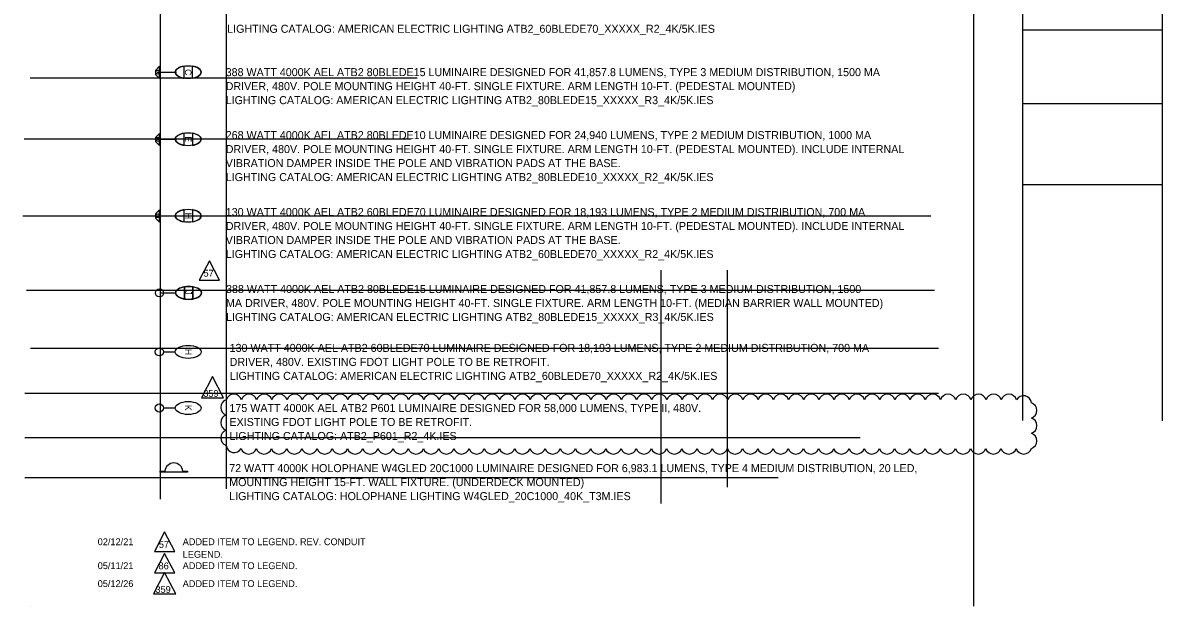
# Model space of a CAD drawing. Extents: x -0.7 to 15.2, y -0.9 to 9.6.
# Drawn here: x -0.62 to 9.35, y -0.9 to 4.21 of the extents above; entities that cross this region are included whole.
import ezdxf

# ---------------------------------------------------------------- set-up
doc = ezdxf.new("R2010")
doc.units = 0
for name, color, linetype in [('ActivePointCell_dp', 7, 'Continuous'), ('AdhocPoint_dp', 7, 'Continuous'), ('Cloud_dp', 7, 'Continuous'), ('LightingMisc', 7, 'Continuous'), ('Miscellaneous2', 7, 'Continuous'), ('Miscellaneous3', 7, 'Continuous'), ('Miscellaneous8', 7, 'Continuous'), ('Miscellaneous9', 7, 'Continuous'), ('ScratchEle_dp', 7, 'Continuous'), ('TextMisc', 7, 'Continuous'), ('TextShtNo', 7, 'Continuous')]:
    doc.layers.add(name, color=color, linetype=linetype)

msp = doc.modelspace()

# ---------------------------------------------------------------- linework, layer by layer
at = {"layer": 'ActivePointCell_dp'}
for p, q in [((7.7, -0.9), (7.7, 9.6)), ((8.1255, 9.4869), (8.1255, 0.7251)), ((9.3472, 9.4838), (9.3472, 0.7219)), ((0.5844, 9.2534), (0.5844, 0.0367)), ((1.1641, 0.1282), (1.1641, 9.1337)), ((2.8316, 3.722), (-0.5519, 3.722)), ((2.7789, 3.1858), (-0.6046, 3.1858)), ((7.3238, 2.5135), (-0.6178, 2.5135)), ((4.9633, 2.0414), (4.9633, 0)), ((5.5423, 2.0414), (5.5423, 0.1403)), ((7.3568, 1.862), (-0.5847, 1.862)), ((7.39, 1.3545), (-0.5516, 1.3545)), ((7.39, 0.9614), (-0.599, 0.9614)), ((6.7052, 0.5747), (-0.599, 0.5747)), ((5.9878, 0.2247), (-0.599, 0.2247))]:
    msp.add_line(p, q, dxfattribs=at)
at = {"layer": 'Cloud_dp'}
for points in [[(1.0137, 2.1234), (0.9257, 1.9538), (1.1017, 1.9538)], [(1.0412, 1.1101), (0.9444, 0.9236), (1.138, 0.9236)], [(0.6228, -0.2504), (0.5348, -0.42), (0.7109, -0.42)], [(0.6228, -0.4378), (0.5348, -0.6074), (0.7109, -0.6074)], [(0.6228, -0.6056), (0.526, -0.7921), (0.7197, -0.7921)]]:
    msp.add_lwpolyline(points, close=True, dxfattribs=at)
for centre, radius, start, end in [((1.1825, 0.8395), 0.0697, 107.5, 252.5), ((1.228, 0.885), 0.0697, 17.5, 162.5), ((1.3609, 0.885), 0.0697, 17.5, 162.5), ((1.4939, 0.885), 0.0697, 17.5, 162.5), ((1.6268, 0.885), 0.0697, 17.5, 162.5), ((1.7597, 0.885), 0.0697, 17.5, 162.5), ((1.8926, 0.885), 0.0697, 17.5, 162.5), ((2.0255, 0.885), 0.0697, 17.5, 162.5), ((2.1584, 0.885), 0.0697, 17.5, 162.5), ((2.2913, 0.885), 0.0697, 17.5, 162.5), ((2.4242, 0.885), 0.0697, 17.5, 162.5), ((2.5571, 0.885), 0.0697, 17.5, 162.5), ((2.69, 0.885), 0.0697, 17.5, 162.5), ((2.8229, 0.885), 0.0697, 17.5, 162.5), ((2.9559, 0.885), 0.0697, 17.5, 162.5), ((3.0888, 0.885), 0.0697, 17.5, 162.5), ((3.2217, 0.885), 0.0697, 17.5, 162.5), ((3.3546, 0.885), 0.0697, 17.5, 162.5), ((3.4875, 0.885), 0.0697, 17.5, 162.5), ((3.6204, 0.885), 0.0697, 17.5, 162.5), ((3.7533, 0.885), 0.0697, 17.5, 162.5), ((3.8862, 0.885), 0.0697, 17.5, 162.5), ((4.0191, 0.885), 0.0697, 17.5, 162.5), ((4.152, 0.885), 0.0697, 17.5, 162.5), ((4.2849, 0.885), 0.0697, 17.5, 162.5), ((4.4178, 0.885), 0.0697, 17.5, 162.5), ((4.5508, 0.885), 0.0697, 17.5, 162.5), ((4.6837, 0.885), 0.0697, 17.5, 162.5), ((4.8166, 0.885), 0.0697, 17.5, 162.5), ((4.9495, 0.885), 0.0697, 17.5, 162.5), ((5.0824, 0.885), 0.0697, 17.5, 162.5), ((5.2153, 0.885), 0.0697, 17.5, 162.5), ((5.3482, 0.885), 0.0697, 17.5, 162.5), ((5.4811, 0.885), 0.0697, 17.5, 162.5), ((5.614, 0.885), 0.0697, 17.5, 162.5), ((5.7469, 0.885), 0.0697, 17.5, 162.5), ((5.8798, 0.885), 0.0697, 17.5, 162.5), ((6.0128, 0.885), 0.0697, 17.5, 162.5), ((6.1457, 0.885), 0.0697, 17.5, 162.5), ((6.2786, 0.885), 0.0697, 17.5, 162.5), ((6.4115, 0.885), 0.0697, 17.5, 162.5), ((6.5444, 0.885), 0.0697, 17.5, 162.5), ((6.6773, 0.885), 0.0697, 17.5, 162.5), ((6.8102, 0.885), 0.0697, 17.5, 162.5), ((6.9431, 0.885), 0.0697, 17.5, 162.5), ((7.076, 0.885), 0.0697, 17.5, 162.5), ((7.2089, 0.885), 0.0697, 17.5, 162.5), ((7.3418, 0.885), 0.0697, 17.5, 162.5), ((7.4748, 0.885), 0.0697, 17.5, 162.5), ((7.6077, 0.885), 0.0697, 17.5, 162.5), ((7.7406, 0.885), 0.0697, 17.5, 162.5), ((7.8735, 0.885), 0.0697, 17.5, 162.5), ((8.0064, 0.885), 0.0697, 17.5, 162.5), ((8.1337, 0.8722), 0.0696, 5.94047, 150.94047), ((8.182, 0.8129), 0.0697, 287.5, 72.5), ((1.1825, 0.7066), 0.0697, 107.5, 252.5), ((8.182, 0.68), 0.0697, 287.5, 72.5), ((1.1825, 0.5737), 0.0697, 107.5, 252.5), ((8.182, 0.5471), 0.0697, 287.5, 72.5), ((1.2308, 0.5145), 0.0696, 185.94047, 330.94047), ((1.3582, 0.5016), 0.0697, 197.5, 342.5), ((1.4911, 0.5016), 0.0697, 197.5, 342.5), ((1.624, 0.5016), 0.0697, 197.5, 342.5), ((1.7569, 0.5016), 0.0697, 197.5, 342.5), ((1.8898, 0.5016), 0.0697, 197.5, 342.5), ((2.0227, 0.5016), 0.0697, 197.5, 342.5), ((2.1556, 0.5016), 0.0697, 197.5, 342.5), ((2.2885, 0.5016), 0.0697, 197.5, 342.5), ((2.4214, 0.5016), 0.0697, 197.5, 342.5), ((2.5543, 0.5016), 0.0697, 197.5, 342.5), ((2.6873, 0.5016), 0.0697, 197.5, 342.5), ((2.8202, 0.5016), 0.0697, 197.5, 342.5), ((2.9531, 0.5016), 0.0697, 197.5, 342.5), ((3.086, 0.5016), 0.0697, 197.5, 342.5), ((3.2189, 0.5016), 0.0697, 197.5, 342.5), ((3.3518, 0.5016), 0.0697, 197.5, 342.5), ((3.4847, 0.5016), 0.0697, 197.5, 342.5), ((3.6176, 0.5016), 0.0697, 197.5, 342.5), ((3.7505, 0.5016), 0.0697, 197.5, 342.5), ((3.8834, 0.5016), 0.0697, 197.5, 342.5), ((4.0163, 0.5016), 0.0697, 197.5, 342.5), ((4.1493, 0.5016), 0.0697, 197.5, 342.5), ((4.2822, 0.5016), 0.0697, 197.5, 342.5), ((4.4151, 0.5016), 0.0697, 197.5, 342.5), ((4.548, 0.5016), 0.0697, 197.5, 342.5), ((4.6809, 0.5016), 0.0697, 197.5, 342.5), ((4.8138, 0.5016), 0.0697, 197.5, 342.5), ((4.9467, 0.5016), 0.0697, 197.5, 342.5), ((5.0796, 0.5016), 0.0697, 197.5, 342.5), ((5.2125, 0.5016), 0.0697, 197.5, 342.5), ((5.3454, 0.5016), 0.0697, 197.5, 342.5), ((5.4783, 0.5016), 0.0697, 197.5, 342.5), ((5.6112, 0.5016), 0.0697, 197.5, 342.5), ((5.7442, 0.5016), 0.0697, 197.5, 342.5), ((5.8771, 0.5016), 0.0697, 197.5, 342.5), ((6.01, 0.5016), 0.0697, 197.5, 342.5), ((6.1429, 0.5016), 0.0697, 197.5, 342.5), ((6.2758, 0.5016), 0.0697, 197.5, 342.5), ((6.4087, 0.5016), 0.0697, 197.5, 342.5), ((6.5416, 0.5016), 0.0697, 197.5, 342.5), ((6.6745, 0.5016), 0.0697, 197.5, 342.5), ((6.8074, 0.5016), 0.0697, 197.5, 342.5), ((6.9403, 0.5016), 0.0697, 197.5, 342.5), ((7.0732, 0.5016), 0.0697, 197.5, 342.5), ((7.2062, 0.5016), 0.0697, 197.5, 342.5), ((7.3391, 0.5016), 0.0697, 197.5, 342.5), ((7.472, 0.5016), 0.0697, 197.5, 342.5), ((7.6049, 0.5016), 0.0697, 197.5, 342.5), ((7.7378, 0.5016), 0.0697, 197.5, 342.5), ((7.8707, 0.5016), 0.0697, 197.5, 342.5), ((8.0036, 0.5016), 0.0697, 197.5, 342.5), ((8.1365, 0.5016), 0.0697, 197.5, 342.5)]:
    msp.add_arc(centre, radius, start, end, dxfattribs=at)
at = {"layer": 'LightingMisc'}
for p, q in [((0.584, 0.2734), (0.5839, 0.2814)), ((0.5839, 0.2814), (0.6241, 0.2814)), ((0.8228, 0.2739), (0.584, 0.2734)), ((0.7826, 0.2818), (0.8228, 0.2819)), ((0.8228, 0.2819), (0.8228, 0.2739))]:
    msp.add_line(p, q, dxfattribs=at)
msp.add_arc((0.7034, 0.2737), 0.0796, 5.86956, 174.39115, dxfattribs=at)
at = {"layer": 'Miscellaneous2'}
msp.add_ellipse((0.8323, 1.8418), major_axis=(-0.1133, 0), ratio=0.5, start_param=4.391241, end_param=4.391271, dxfattribs=at)
at = {"layer": 'Miscellaneous3'}
msp.add_line((8.1215, 4.1449), (9.3431, 4.1449), dxfattribs=at)
at = {"layer": 'Miscellaneous8'}
msp.add_line((8.1215, 3.4986), (9.342, 3.4986), dxfattribs=at)
at = {"layer": 'Miscellaneous9'}
msp.add_line((8.122, 2.7896), (9.3437, 2.7896), dxfattribs=at)
at = {"layer": 'ScratchEle_dp'}
for p, q in [((0.7932, 3.7193), (0.7932, 3.8268)), ((0.8647, 3.8268), (0.8647, 3.7193)), ((0.5583, 3.7731), (0.7274, 3.7731)), ((0.7936, 3.132), (0.7936, 3.2395)), ((0.8651, 3.2395), (0.8651, 3.132)), ((0.5587, 3.1858), (0.7277, 3.1858)), ((0.5587, 2.5167), (0.7277, 2.5167)), ((0.7936, 2.463), (0.7936, 2.5705)), ((0.8651, 2.5705), (0.8651, 2.463)), ((0.7965, 1.7881), (0.7965, 1.8956)), ((0.7965, 1.8944), (0.7965, 1.7881)), ((0.868, 1.8956), (0.868, 1.7881)), ((0.868, 1.7881), (0.868, 1.8956)), ((0.5929, 1.8415), (0.7238, 1.8415)), ((0.6113, 1.3255), (0.7161, 1.3255)), ((0.6113, 0.8345), (0.7161, 0.8345))]:
    msp.add_line(p, q, dxfattribs=at)
for points in [[(0.5425, 3.789), (0.5426, 3.7532), (0.5783, 3.7175), (0.5782, 3.8248)], [(0.5429, 3.2017), (0.543, 3.1659), (0.5786, 3.1302), (0.5786, 3.2374)], [(0.5429, 2.5327), (0.543, 2.4969), (0.5786, 2.4612), (0.5786, 2.5684)]]:
    msp.add_lwpolyline(points, close=True, dxfattribs=at)
for centre, radius in [((0.5617, 3.7728), 0.0163), ((0.562, 3.1855), 0.0163), ((0.562, 2.5165), 0.0163), ((0.5779, 1.8415), 0.0354), ((0.5779, 1.8415), 0.0354), ((0.576, 1.3255), 0.0354), ((0.576, 0.8345), 0.0354)]:
    msp.add_circle(centre, radius, dxfattribs=at)
for centre in [(0.8289, 3.7731), (0.8293, 3.1858), (0.8293, 2.5167), (0.8323, 1.8418), (0.8293, 1.3255), (0.8293, 0.8345)]:
    msp.add_ellipse(centre, major_axis=(-0.1133, 0), ratio=0.5, dxfattribs=at)
for centre, start_param, end_param in [((0.8289, 3.7731), 5.033538, 6.283185), ((0.8289, 3.7731), 1.891945, 4.391241), ((0.8289, 3.7731), 0, 0.847605), ((0.8289, 3.7731), 0.847605, 1.249648), ((0.8293, 3.1858), 5.033538, 6.283185), ((0.8293, 3.1858), 1.891945, 4.391241), ((0.8293, 3.1858), 0, 0.847605), ((0.8293, 3.1858), 0.847605, 1.249648), ((0.8293, 2.5167), 5.033538, 6.283185), ((0.8293, 2.5167), 0, 0.847605), ((0.8293, 2.5167), 1.891945, 4.391241), ((0.8293, 2.5167), 0.847605, 1.249648), ((0.8323, 1.8418), 5.033538, 6.283185), ((0.8323, 1.8418), 4.391271, 5.033538), ((0.8323, 1.8418), 1.891945, 4.391241), ((0.8323, 1.8418), 0, 0.847605), ((0.8323, 1.8418), 0.847605, 1.249648), ((0.8323, 1.8418), 1.249648, 1.891946)]:
    msp.add_ellipse(centre, major_axis=(-0.1133, 0), ratio=0.5, start_param=start_param, end_param=end_param, dxfattribs=at)
at = {"layer": 'TextMisc'}
msp.add_line((-0.55, -0.9), (-0.55, -0.9), dxfattribs=at)

# ---------------------------------------------------------------- texts
at = {"layer": 'AdhocPoint_dp'}
for s, p in [('LIGHTING CATALOG: AMERICAN ELECTRIC LIGHTING ATB2_60BLEDE70_XXXXX_R2_4K/5K.IES', (1.1699, 4.1176)), ('388 WATT 4000K AEL ATB2 80BLEDE15 LUMINAIRE DESIGNED FOR 41,857.8 LUMENS, TYPE 3 MEDIUM DISTRIBUTION, 1500 MA ', (1.1566, 3.7381)), ('DRIVER, 480V. POLE MOUNTING HEIGHT 40-FT. SINGLE FIXTURE. ARM LENGTH 10-FT. (PEDESTAL MOUNTED)', (1.1566, 3.6156)), ('LIGHTING CATALOG: AMERICAN ELECTRIC LIGHTING ATB2_80BLEDE15_XXXXX_R3_4K/5K.IES', (1.1566, 3.4931)), ('268 WATT 4000K AEL ATB2 80BLEDE10 LUMINAIRE DESIGNED FOR 24,940 LUMENS, TYPE 2 MEDIUM DISTRIBUTION, 1000 MA ', (1.157, 3.1875)), ('DRIVER, 480V. POLE MOUNTING HEIGHT 40-FT. SINGLE FIXTURE. ARM LENGTH 10-FT. (PEDESTAL MOUNTED). INCLUDE INTERNAL ', (1.157, 3.065)), ('VIBRATION DAMPER INSIDE THE POLE AND VIBRATION PADS AT THE BASE.', (1.157, 2.9425)), ('LIGHTING CATALOG: AMERICAN ELECTRIC LIGHTING ATB2_80BLEDE10_XXXXX_R2_4K/5K.IES', (1.157, 2.82)), ('130 WATT 4000K AEL ATB2 60BLEDE70 LUMINAIRE DESIGNED FOR 18,193 LUMENS, TYPE 2 MEDIUM DISTRIBUTION, 700 MA ', (1.1574, 2.5143)), ('DRIVER, 480V. POLE MOUNTING HEIGHT 40-FT. SINGLE FIXTURE. ARM LENGTH 10-FT. (PEDESTAL MOUNTED). INCLUDE INTERNAL ', (1.1574, 2.3918)), ('VIBRATION DAMPER INSIDE THE POLE AND VIBRATION PADS AT THE BASE.', (1.1574, 2.2693)), ('LIGHTING CATALOG: AMERICAN ELECTRIC LIGHTING ATB2_60BLEDE70_XXXXX_R2_4K/5K.IES', (1.1574, 2.1468)), ('388 WATT 4000K AEL ATB2 80BLEDE15 LUMINAIRE DESIGNED FOR 41,857.8 LUMENS, TYPE 3 MEDIUM DISTRIBUTION, 1500 ', (1.1594, 1.8408)), ('MA DRIVER, 480V. POLE MOUNTING HEIGHT 40-FT. SINGLE FIXTURE. ARM LENGTH 10-FT. (MEDIAN BARRIER WALL MOUNTED)', (1.1594, 1.7183)), ('LIGHTING CATALOG: AMERICAN ELECTRIC LIGHTING ATB2_80BLEDE15_XXXXX_R3_4K/5K.IES', (1.1594, 1.5958)), ('130 WATT 4000K AEL ATB2 60BLEDE70 LUMINAIRE DESIGNED FOR 18,193 LUMENS, TYPE 2 MEDIUM DISTRIBUTION, 700 MA ', (1.1912, 1.3255)), ('DRIVER, 480V. EXISTING FDOT LIGHT POLE TO BE RETROFIT.', (1.1912, 1.203)), ('LIGHTING CATALOG: AMERICAN ELECTRIC LIGHTING ATB2_60BLEDE70_XXXXX_R2_4K/5K.IES', (1.1912, 1.0805)), ('175 WATT 4000K AEL ATB2 P601 LUMINAIRE DESIGNED FOR 58,000 LUMENS, TYPE II, 480V.', (1.1895, 0.7995)), ('EXISTING FDOT LIGHT POLE TO BE RETROFIT.', (1.1895, 0.677)), ('LIGHTING CATALOG: ATB2_P601_R2_4K.IES', (1.1895, 0.5545)), ('72 WATT 4000K HOLOPHANE W4GLED 20C1000 LUMINAIRE DESIGNED FOR 6,983.1 LUMENS, TYPE 4 MEDIUM DISTRIBUTION, 20 LED, ', (1.1877, 0.2734)), ('MOUNTING HEIGHT 15-FT. WALL FIXTURE. (UNDERDECK MOUNTED)', (1.1877, 0.1509)), ('LIGHTING CATALOG: HOLOPHANE LIGHTING W4GLED_20C1000_40K_T3M.IES', (1.1877, 0.0284))]:
    msp.add_text(s, height=0.07, dxfattribs=at).set_placement(p)
at = {"layer": 'Cloud_dp'}
for s, p in [('57', (0.963, 1.984)), ('359', (0.9607, 0.9323)), ('02/12/21', (0.0373, -0.3659)), ('57', (0.5721, -0.3898)), ('ADDED ITEM TO LEGEND. REV. CONDUIT ', (0.7806, -0.3659)), ('LEGEND.', (0.7806, -0.4759)), ('05/11/21', (0.0373, -0.5754)), ('86', (0.5695, -0.5772)), ('ADDED ITEM TO LEGEND.', (0.7806, -0.5754)), ('05/12/26', (0.0373, -0.7324)), ('ADDED ITEM TO LEGEND.', (0.7806, -0.7324)), ('359', (0.5423, -0.7834))]:
    msp.add_text(s, height=0.06, dxfattribs=at).set_placement(p)
at = {"layer": 'TextShtNo'}
for s, rotation, p in [('C', 270.00003, (0.8003, 3.7999)), ('E', 270.00003, (0.8007, 3.2115)), ('H', 270.00003, (0.8007, 2.5429)), ('J', 270.00005, (0.8037, 1.8634)), ('H', 270.00003, (0.8007, 1.3517)), ('K', 270.00003, (0.8007, 0.8616))]:
    msp.add_text(s, height=0.0572, rotation=rotation, dxfattribs=at).set_placement(p)

doc.saveas('drawing.dxf')
